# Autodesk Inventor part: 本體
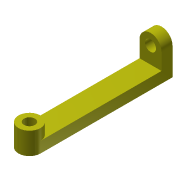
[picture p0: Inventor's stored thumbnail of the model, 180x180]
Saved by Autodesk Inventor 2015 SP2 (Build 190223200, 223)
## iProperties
Created: 2020-03
Part Number: 本體
Material: 一般
Document SubType Name: Modeling
Designer: Kuan-Lun Hsu
Density: 1 g/cm^3
Appearance: 黃
Author: Kuan-Lun Hsu
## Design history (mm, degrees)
sketch "草圖1"
  geometry: L1 (-10, 120)-(10, 120); L2 (10, 120)-(10, -20); L3 (10, -20)-(-10, -20); L4 (-10, -20)-(-10, 120); 2 further points
  constraints: 8 end point, 2 parallel, 1 horizontal, 1 midpoint, 1 perpendicular, 1 vertical alignment
  dimensions: "d0" = 20 distance from line of L3 point (0, 0); "d1" = 140 distance of L3.end L1.start; "d2" = 20 distance of L1.start L1.end
extrude "擠出1" new body sketch "草圖1" distance "d3" = 10; taper "d4" = 0 deg
sketch "草圖2"
  geometry: C1 r 10 at (0, 0); C2 r 5 at (0, 0); 1 further point
  constraints: 2 centre point, 2 coincident
  dimensions: "d5" = 20 diameter of C1; "d6" = 10 diameter of C2
extrude "擠出2" join sketch "草圖2" distance "d7" = 10; taper "d8" = 0 deg
sketch "草圖3" dims "d9" = 20
  geometry: L1 (20, -10)-(0, -10) reference; L2 (0, 0)-(20, 0) reference; L3 (0, 0)-(20, 0); L4 (20, 0)-(20, -25); L5 (20, -25)-(0, -25); L6 (0, -25)-(0, 0); 4 further points
  constraints: 8 end point, 3 midpoint, 2 parallel, 1 horizontal, 1 horizontal alignment, 1 perpendicular, 1 vertical, 1 vertical alignment, 2 other
  dimensions: "d10" = 25 distance from line of L2 point (10, -25)
extrude "擠出3" join sketch "草圖3" distance "d11" = 10; taper "d12" = 0 deg
sketch "草圖4"
  geometry: C1 r 5 at (10, -25); A1 r 10 centre (10, -25) between (0, -25) and (20, -25) reference; 1 further point
  constraints: 1 centre point, 1 coincident
  dimensions: "d13" = 10 diameter of C1
extrude "擠出4" cut sketch "草圖4" distance "d14" = 10; taper "d15" = 0 deg
sketch "草圖5"
  geometry: L1 (-10, 0)-(-10, -20) reference; L2 (-10, -20)-(10, -20) reference; L3 (10, -20)-(10, 0) reference; A1 r 10 centre (0, 0) between (-10, 0) and (10, 0) reference; 1 further point
extrude "擠出5" cut sketch "草圖5" stored distance "d16" = 10; taper "d17" = 0 deg
node "實體1"
node "投影迴路1"
